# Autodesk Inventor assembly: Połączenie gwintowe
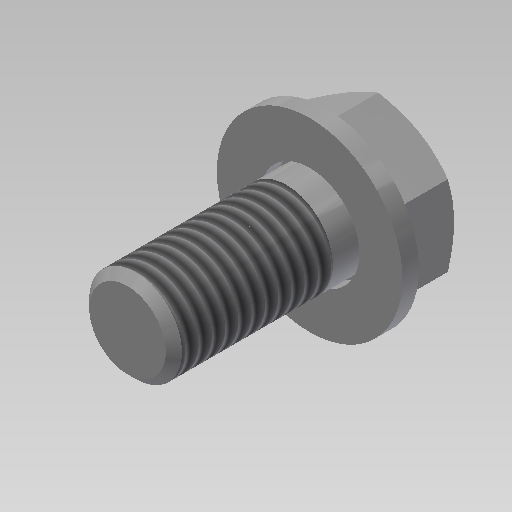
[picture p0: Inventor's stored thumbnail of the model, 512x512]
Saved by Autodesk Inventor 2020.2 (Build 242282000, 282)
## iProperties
Created: 2006-08
Part Number: Połączenie gwintowe
Document SubType Name: Assembly
Designer: F.Stasiak
ClientObjectVersion: 1
Manager: www.cadconsulting.pl
Company: Fabian Stasiak CAD Consulting
Author: F.Stasiak
Subject: Zbiór ćwiczeń. Autodesk Inventor 2020. Kurs podstawowy
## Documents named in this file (3)
- C:\2020_Kurs_podstawowy\R6 Zespoły\BOM\123-000-000\Design Accelerator\Połączenie gwintowe2.iam
- C:\2020_Kurs_podstawowy\Zasoby\Content Center Files\pl-PL\DIN 125-1  A\14.ipt
- C:\2020_Kurs_podstawowy\Zasoby\Content Center Files\pl-PL\DIN EN 24 017\M14-30.ipt
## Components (2 placed, 2 different names)
1. DIN 125-1  A A 15:1
2. DIN EN 24 017 M14 x 30:1
